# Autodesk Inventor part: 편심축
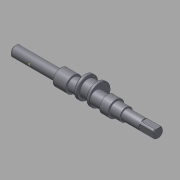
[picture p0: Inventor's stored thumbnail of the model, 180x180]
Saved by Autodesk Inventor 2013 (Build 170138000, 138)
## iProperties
Company: 한국ATC센터
Created: 2015-12
Part Number: 편심축
Document SubType Name: Modeling
Designer: mdu
Density: 7.86 g/cm^3
Mass: 232.042 g
Surface Area: 95.131 cm^2
Volume: 29.5219 cm^3
Material: 강철, 연강
Author: mdu
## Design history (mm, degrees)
sketch "스케치1"
  geometry: L1 (-84.5, 0)-(84.5, 0); L2 (-84.5, 0)-(-84.5, 6); L3 (-84.5, 6)-(-30.5, 6); L4 (-30.5, 6)-(-30.5, 9.5); L5 (-30.5, 9.5)-(-15.5, 9.5); L6 (-15.5, 9.5)-(-15.5, 7.5); L7 (-15.5, 7.5)-(46.5, 7.5); L8 (84.5, 6)-(84.5, 0); L9 (34.5, 7.5)-(34.5, 9.5); L10 (34.5, 9.5)-(24.5, 9.5); L11 (24.5, 9.5)-(24.5, 7.5); L12 (46.5, 7.5)-(46.5, 6); L13 (46.5, 6)-(84.5, 6); 2 further points
  constraints: 26 end point, 6 parallel, 6 perpendicular, 2 point on line, 1 coincident, 1 horizontal, 1 midpoint
  dimensions: "d1" = 12 diameter of L3 L1; "d2" = 15 diameter of L7 L1; "d4" = 15 distance of L4.end L5.end; "d5" = 19 diameter of L5 L1; "d24" = 10 distance of L9.end L10.end; "d25" = 19 diameter of L10 L1; "d27" = 40 distance between parallel lines of L11 L6; "d28" = 54 distance of L2.end L3.end; "d29" = 50 distance between parallel lines of L8 L9; "d41" = 38 distance between parallel lines of L8 L12; "d42" = 12 diameter of L13 L1
revolve "회전1" stored, may be unused: angle "d6" = 90 deg
node "작업 평면1"
sketch "스케치2"
  geometry: C1 r 7.5 at (0, 0) reference; C2 r 12.5 at (0, 4.5); 1 further point
  constraints: 1 centre point, 1 vertical alignment
  dimensions: "d8" = 4.5 distance of point (0, 0) C2.centre; "d9" = 25 diameter of C2
extrude "돌출1" join sketch "스케치2" distance "d10" = 18; taper "d11" = 0 deg
chamfer "모따기1" distance "d12" = 1; stored, may be unused: second distance "d13" = 2, angle "d14" = 45 deg
chamfer "모따기2" distance "d15" = 0.5; stored, may be unused: second distance "d16" = 2, angle "d17" = 45 deg
node "작업 평면2"
sketch "스케치3"
  geometry: L1 (4, -2)-(18, -2); L2 (18, 2)-(4, 2); L3 (27, 5)-(27, -5) reference; A1 r 2 centre (18, 0) between (18, -2) and (18, 2); A2 r 2 centre (4, 0) between (4, 2) and (4, -2); 2 further points
  constraints: 4 end point, 4 point on circle, 4 tangent, 2 centre point, 1 horizontal, 1 horizontal alignment, 1 midpoint, 1 parallel
  dimensions: "d18" = 7 distance edge to line of A1 L3; "d19" = 4 distance between parallel lines of L2 L1; "d20" = 18 dimension on A1 A2
extrude "돌출2" cut sketch "스케치3" distance "d21" = 2.5; taper "d22" = 0 deg
revolve "회전2" stored, may be unused: angle "d26" = 90 deg
node "작업 평면3"
sketch "스케치10"
  geometry: L1 (-5, -5)-(5, -5); L2 (5, -5)-(5, 5); L3 (5, 5)-(-5, 5); L4 (-5, 5)-(-5, -5); L5 (-5, -5)-(5, 5); L6 (5, -5)-(-5, 5); C1 r 5 at (0, 0) reference; C2 r 6 at (0, 0) reference; A1 r 6 centre (0, 0) between (5, 3.317) and (3.317, 5); A2 r 6 centre (0, 0) between (5, -3.317) and (5, 3.317); A3 r 6 centre (0, 0) between (3.317, -5) and (5, -3.317); A4 r 6 centre (0, 0) between (-3.317, -5) and (3.317, -5); A5 r 6 centre (0, 0) between (-5, -3.317) and (-3.317, -5); A6 r 6 centre (0, 0) between (-5, 3.317) and (-5, -3.317); A7 r 6 centre (0, 0) between (-3.317, 5) and (-5, 3.317); A8 r 6 centre (0, 0) between (3.317, 5) and (-3.317, 5)
  constraints: 16 point on circle, 12 end point, 8 centre point, 8 point on line, 2 midpoint, 2 parallel, 2 tangent, 1 coincident, 1 concentric, 1 horizontal, 1 perpendicular
extrude "돌출4" cut sketch "스케치10" distance "d55" = 17; taper "d56" = 0 deg
sketch "스케치6"
  geometry: L1 (-83.5, -6)-(-30.5, -6) reference; L2 (-84.5, -5)-(-84.5, 5) reference; L3 (-83.5, 6)-(-30.5, 6) reference; L4 (-62.5, 6)-(-62.5, -6); L5 (-62.5, -6)-(-61, -6); L6 (-62.5, -4.5)-(-61, -6); L7 (-62.5, -6)-(-62.5, -4.5); 2 further points
  constraints: 8 end point, 4 point on line, 2 perpendicular, 1 coincident
  dimensions: "d43" = 22 distance between parallel lines of L4 L2; "d44" = 45 deg angle of L6 L7; "d45" = 3 diameter of L5.end L4
revolve "회전3" stored, may be unused: angle "d46" = 90 deg
node "작업점1"
node "작업 평면5"
sketch "스케치11"
  geometry: C1 r 12.5 at (0, 0) reference; C2 r 9.5 at (0, 0); 1 further point
  constraints: 1 centre point
  dimensions: "d57" = 3 radial gap between concentric circles of C1 C2
extrude "돌출5" cut sketch "스케치11" stored distance "d58" = 11; taper "d59" = 0 deg
fillet "모깎기1" dims "d60" = 0.3
chamfer "모따기4" distance "d61" = 0.5; stored, may be unused: second distance "d62" = 2, angle "d63" = 45 deg
node "솔리드1"
node "절단 모서리 투영2"
other parameters: "d7" = 8.5
